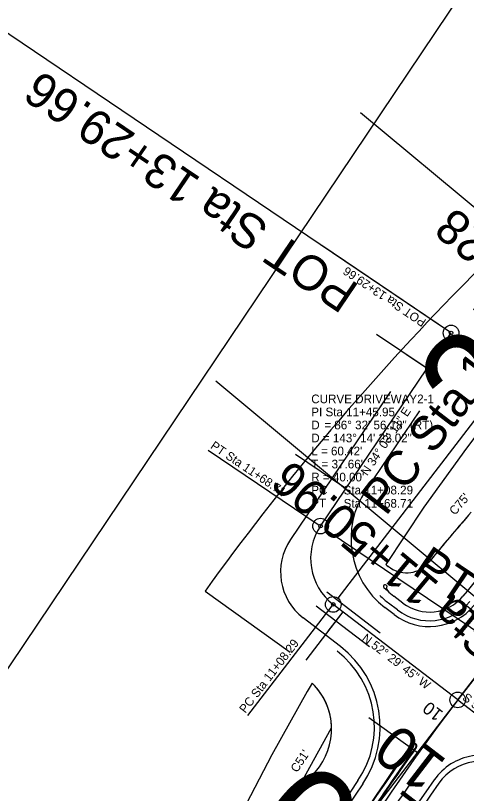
# Model space of a CAD drawing. Extents: x 2358865 to 2362945, y 393485 to 404880.
# Drawn here: x 2359255 to 2359566, y 397834 to 398371 of the extents above; entities that cross this region are included whole.
import ezdxf

# ---------------------------------------------------------------- set-up
doc = ezdxf.new("R2010")
doc.units = 0
for name, color, linetype in [('CL', 7, 'Continuous'), ('Level 11', 7, 'Continuous'), ('Level 12', 7, 'Continuous'), ('Level 19', 7, 'Continuous'), ('Level 21', 7, 'Continuous'), ('Level 22', 7, 'Continuous'), ('Level 25', 7, 'Continuous'), ('Level 27', 7, 'Continuous'), ('Level 28', 7, 'Continuous'), ('Level 30', 7, 'Continuous'), ('Level 36', 7, 'Continuous'), ('Level 37', 7, 'Continuous'), ('Level 39', 7, 'Continuous'), ('Level 40', 7, 'Continuous'), ('Level 41', 7, 'Continuous'), ('Level 48', 7, 'Continuous'), ('Level 50', 7, 'Continuous'), ('Level 53', 7, 'Continuous'), ('Level 61', 7, 'Continuous'), ('Level 63', 7, 'Continuous')]:
    doc.layers.add(name, color=color, linetype=linetype)

msp = doc.modelspace()

# ---------------------------------------------------------------- linework, layer by layer
at = {"layer": 'CL'}
for p, q in [((2359465.41, 398018.19), (2359555.54, 398151.53)), ((2359560.1, 397898.13), (2359474.2, 397964.06)), ((2359560.1, 397898.13), (2359606.99, 397862.15))]:
    msp.add_line(p, q, dxfattribs=at)
for centre, radius, start, end in [((2360835.02, 396931.39), 1600, 135.75191, 198.12413), ((2359498.55, 397995.79), 40, 145.9468, 232.4958)]:
    msp.add_arc(centre, radius, start, end, dxfattribs=at)
at = {"layer": 'Level 11'}
msp.add_line((2359518.58, 397960.25), (2359512.33, 397965.05), dxfattribs=at)
for centre, radius, start, end in [((2359546.42, 398009.47), 56, 224.449, 232.4958), ((2359540.5, 397988.81), 36, 232.4958, 320.7568), ((2359436.6, 397879.46), 66, 325.8644, 52.4958), ((2359576.6, 397819.94), 36, 53.3123, 144.775), ((2360835.02, 396931.39), 1623.5, 145.86442, 156.63495), ((2360835.02, 396931.39), 1576.5, 144.77495, 156.63628)]:
    msp.add_arc(centre, radius, start, end, dxfattribs=at)
at = {"layer": 'Level 12'}
for p, q in [((2359509.2, 397975.69), (2359511.56, 397973.63)), ((2359522.24, 397965.01), (2359515.98, 397969.81))]:
    msp.add_line(p, q, dxfattribs=at)
for centre, radius, start, end in [((2360835.02, 396931.39), 1641.5, 135.75153, 140.75675), ((2359509.96, 397976.55), 1.15, 48.8985, 228.9007), ((2359546.42, 398009.47), 50, 225.7868, 232.4958), ((2359540.5, 397988.81), 30, 232.4958, 320.7568)]:
    msp.add_arc(centre, radius, start, end, dxfattribs=at)
msp.add_spline([(2359510.71, 397977.41), (2359510.9, 397977.25), (2359511.15, 397976.4), (2359510.96, 397976.03), (2359510.89, 397975.18), (2359511.2, 397974.64), (2359511.49, 397974.16), (2359511.56, 397973.63)], degree=3, dxfattribs=at)
at = {"layer": 'Level 19'}
for p, q in [((2359513.8, 398111.21), (2359444.66, 398008.9)), ((2359533.69, 398097.78), (2359496.71, 398043.07)), ((2359516.15, 397957.07), (2359509.9, 397961.87)), ((2359479.22, 397934.99), (2359453.44, 397954.77))]:
    msp.add_line(p, q, dxfattribs=at)
for centre, radius, start, end in [((2359546.42, 398009.47), 60, 145.9468, 232.4958), ((2359477.8, 397986.51), 40, 145.9468, 232.4958), ((2359540.5, 397988.81), 40, 232.4958, 320.7568), ((2359436.6, 397879.46), 70, 325.8644, 52.4958), ((2359576.6, 397819.94), 40, 53.3123, 144.775), ((2360835.02, 396931.39), 1580.5, 144.77495, 156.63495), ((2360835.02, 396931.39), 1619.5, 145.86442, 156.63495)]:
    msp.add_arc(centre, radius, start, end, dxfattribs=at)
at = {"layer": 'Level 25'}
for p, q in [((2359538.93, 398126.96), (2359534.79, 398129.76)), ((2359482.93, 398044.11), (2359478.79, 398046.91)), ((2359480.77, 397959.01), (2359477.73, 397955.04)), ((2359560.1, 397898.13), (2359564.98, 397904.48)), ((2359560.1, 397898.13), (2359555.23, 397891.78)), ((2359532.97, 397861.26), (2359528.9, 397864.17))]:
    msp.add_line(p, q, dxfattribs=at)
at = {"layer": 'Level 27'}
for p, q in [((2359556.38, 398176.9), (2359656.09, 398279.26)), ((2359385.67, 397973.31), (2359444.39, 397931.1))]:
    msp.add_line(p, q, dxfattribs=at)
for radius, start, end in [(1785, 135.75191, 144.28807), (1525, 137.30515, 198.12413)]:
    msp.add_arc((2360835.02, 396931.39), radius, start, end, dxfattribs=at)
at = {"layer": 'Level 28'}
for p, q in [((2359554.5, 398152.23), (2359466.26, 398211.87)), ((2359387.78, 398070.66), (2359464.38, 398018.89)), ((2359415.09, 397887.3), (2359473.32, 397963.17))]:
    msp.add_line(p, q, dxfattribs=at)
for centre in [(2359555.54, 398151.53), (2359465.41, 398018.19), (2359474.2, 397964.06)]:
    msp.add_circle(centre, 1.25, dxfattribs=at)
at = {"layer": 'Level 30'}
msp.add_line((2359532.97, 397861.26), (2359526.06, 397866.2), dxfattribs=at)
at = {"layer": 'Level 36'}
msp.add_arc((2360835.02, 396931.39), 1592.5, 144.77495, 149.75265, dxfattribs=at)
at = {"layer": 'Level 37'}
for p, q in [((2359506.46, 397944.34), (2359469.76, 397972.5)), ((2359499.15, 397934.82), (2359462.45, 397962.99))]:
    msp.add_line(p, q, dxfattribs=at)
for centre, radius, start, end in [((2360835.02, 396931.39), 1607.5, 144.381, 156.63113), ((2360835.02, 396931.39), 1607, 144.38099, 156.63113), ((2360835.02, 396931.39), 1604, 144.381, 149.75265), ((2360835.02, 396931.39), 1603.5, 144.381, 149.75265), ((2359529.9, 397866.42), 2, 324.4067, 144.4067), ((2359529.9, 397866.42), 1.5, 324.4067, 144.4067)]:
    msp.add_arc(centre, radius, start, end, dxfattribs=at)
at = {"layer": 'Level 39'}
for p, q in [((2359538.93, 398126.96), (2359524.85, 398136.48)), ((2359482.93, 398044.11), (2359468.85, 398053.63)), ((2359480.77, 397959.01), (2359470.42, 397945.52)), ((2359560.1, 397898.13), (2359579.59, 397923.52)), ((2359560.1, 397898.13), (2359540.62, 397872.74)), ((2359532.97, 397861.26), (2359519.14, 397871.14))]:
    msp.add_line(p, q, dxfattribs=at)
at = {"layer": 'Level 40'}
for p, q in [((2359551.06, 398154.56), (2359202.24, 398390.31)), ((2359817.48, 398033.38), (2359493, 398303.51)), ((2359477.49, 397968.34), (2359707.35, 398267.86)), ((2359563.39, 397902.41), (2359818.86, 398235.29)), ((2359685.48, 397874.82), (2359393.13, 398118.19)), ((2359469.89, 398015.16), (2359772.13, 397810.89)), ((2359556.82, 397893.84), (2359301.35, 397560.97))]:
    msp.add_line(p, q, dxfattribs=at)
for centre in [(2359555.54, 398151.53), (2359465.41, 398018.19), (2359474.2, 397964.06), (2359560.1, 397898.13), (2359560.1, 397898.13)]:
    msp.add_circle(centre, 5.4, dxfattribs=at)
at = {"layer": 'Level 41'}
for p, q in [((2359538.93, 398126.96), (2359504.13, 398150.48)), ((2359482.93, 398044.11), (2359448.14, 398067.63)), ((2359593.59, 397940.77), (2359561.01, 397967.27)), ((2359560.1, 397898.13), (2359608.81, 397961.59)), ((2359480.77, 397959.01), (2359455.2, 397925.69)), ((2359560.1, 397898.13), (2359511.4, 397834.66)), ((2359532.97, 397861.26), (2359498.79, 397885.67))]:
    msp.add_line(p, q, dxfattribs=at)
at = {"layer": 'Level 48'}
for centre, radius, start, end in [((2360835.02, 396931.39), 1607, 144.38099, 156.63097), ((2360835.02, 396931.39), 1604, 144.38097, 149.75265), ((2359529.9, 397866.42), 1.5, 324.381, 144.4067)]:
    msp.add_arc(centre, radius, start, end, dxfattribs=at)
at = {"layer": 'Level 50'}
msp.add_line((2359427.86, 397808.99), (2359461.91, 397848.57), dxfattribs=at)
for centre, radius, start, end in [((2360834.47, 396930.74), 1674.49, 139.0676, 140.61661), ((2359524.77, 398005.9), 20, 236.1711, 320.6166), ((2359546.29, 398038.01), 58.65, 232.7268, 236.1711), ((2359428.54, 397877.95), 44.47, 318.6427, 45.2494)]:
    msp.add_arc(centre, radius, start, end, dxfattribs=at)
at = {"layer": 'Level 61'}
for p, q in [((2359596.04, 398112.17), (2359566.13, 398071.88)), ((2359566.13, 398071.88), (2359536.77, 398031.14)), ((2359536.77, 398031.14), (2359510.46, 397991.57)), ((2359459.59, 397909.77), (2359456.15, 397904.07)), ((2359456.15, 397904.07), (2359431.82, 397860.31)), ((2359455.42, 397847.19), (2359472.99, 397878.83)), ((2359431.82, 397860.31), (2359408.56, 397815.96)), ((2359447.13, 397831.39), (2359455.42, 397847.19))]:
    msp.add_line(p, q, dxfattribs=at)
for centre, radius, start, end in [((2360834.47, 396930.74), 1674.49, 139.23944, 140.61661), ((2359524.77, 398005.9), 20, 236.1711, 320.6166), ((2359546.29, 398038.01), 58.65, 232.3446, 236.1711), ((2359428.54, 397877.95), 44.47, 1.1347, 45.7036)]:
    msp.add_arc(centre, radius, start, end, dxfattribs=at)
at = {"layer": 'Level 63'}
msp.add_lwpolyline([(2360368.8, 398162.59), (2359965.31, 398555.63), (2359965.31, 398555.63), (2359790.77, 398725.65), (2358929.05, 397443.49), (2359114.5, 397249.02), (2359262.02, 397221.84), (2359690.04, 397142.97), (2359690.04, 397142.97)], close=True, dxfattribs=at)

# ---------------------------------------------------------------- texts
at = {"layer": 'Level 21'}
for s, rotation, p in [('N 34%%d 03\' 11" E', 55.9468, (2359497.67, 398052.53)), ('N 34%%d 03\' 11" E', 55.9468, (2359497.67, 398052.53)), ('N 52%%d 29\' 45" W', 322.4958, (2359493.46, 397939.59)), ("S 52%%d 29'", 322.4958, (2359562.85, 397898.65))]:
    msp.add_text(s, height=6, rotation=rotation, dxfattribs=at).set_placement(p)
at = {"layer": 'Level 22'}
for s, p in [('CURVE DRIVEWAY2-1', (2359459, 398103)), ('CURVE DRIVEWAY2-1', (2359459, 398103)), ('PI Sta 11+45.95', (2359459, 398094)), ('PI Sta 11+45.95', (2359459, 398094)), ('D', (2359459, 398085)), ('D', (2359459, 398085)), ('= 86%%d 32\' 56.18" (RT)', (2359468, 398085)), ('= 86%%d 32\' 56.18" (RT)', (2359468, 398085)), ('D = 143%%d 14\' 22.02"', (2359459, 398076.01)), ('D = 143%%d 14\' 22.02"', (2359459, 398076.01)), ("L = 60.42'", (2359459, 398067.02)), ("L = 60.42'", (2359459, 398067.02)), ("T = 37.66'", (2359459, 398058.02)), ("T = 37.66'", (2359459, 398058.02)), ("R = 40.00'", (2359459, 398049.03)), ("R = 40.00'", (2359459, 398049.03)), ('PC', (2359459, 398040.03)), ('PC', (2359459, 398040.03)), ('Sta 11+08.29', (2359481.33, 398040.05)), ('Sta 11+08.29', (2359481.33, 398040.05)), ('PT', (2359459, 398031.04)), ('PT', (2359459, 398031.04)), ('Sta 11+68.71', (2359481.33, 398030.91)), ('Sta 11+68.71', (2359481.33, 398030.91))]:
    msp.add_text(s, height=6, dxfattribs=at).set_placement(p)
at = {"layer": 'Level 25'}
msp.add_text('10', height=8.75, rotation=142.4958, dxfattribs=at).set_placement((2359550.66, 397889.68))
at = {"layer": 'Level 28'}
for s, rotation, p in [('POT Sta 13+29.66', 145.9468, (2359538.88, 398160.38)), ('PT Sta 11+68.71', 325.9468, (2359388.9, 398072.31)), ('PC Sta 11+08.29', 52.4958, (2359413.5, 397888.52))]:
    msp.add_text(s, height=6, rotation=rotation, dxfattribs=at).set_placement(p)
at = {"layer": 'Level 39'}
msp.add_text('10', height=30, rotation=142.4958, dxfattribs=at).set_placement((2359553.73, 397855.88))
at = {"layer": 'Level 40'}
for s, rotation, p in [('POT Sta 13+29.66', 145.9468, (2359493.06, 398184.1)), ('POT Sta 13+57.28', 140.223, (2359762.71, 398068.56)), ('PC Sta 11+08.29', 52.4958, (2359510.47, 398024.46)), ('PT Sta 11+50.96', 140.223, (2359630.71, 397910)), ('PT Sta 11+68.71', 325.9468, (2359527.89, 397985.62)), ('POT Sta 10+00.00', 232.4958, (2359523.83, 397837.73))]:
    msp.add_text(s, height=24, rotation=rotation, dxfattribs=at).set_placement(p)
at = {"layer": 'Level 41'}
for s, rotation, p in [('255', 45.7519, (2359579.58, 398069.59)), ('10', 142.4958, (2359544.28, 397792.41))]:
    msp.add_text(s, height=75, rotation=rotation, dxfattribs=at).set_placement(p)
at = {"layer": 'Level 53'}
for s, rotation, p in [("C75'", 49.0957, (2359558.2, 398025.32)), ("C51'", 56.258, (2359449.2, 397847.54))]:
    msp.add_text(s, height=6, rotation=rotation, dxfattribs=at).set_placement(p)

doc.saveas('drawing.dxf')
